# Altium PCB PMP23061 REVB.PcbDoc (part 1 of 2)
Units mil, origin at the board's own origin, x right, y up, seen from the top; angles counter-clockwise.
Board outline 3200 x 3250 mil, 2 copper layers (Top Layer, Bottom Layer), stack 64.8 mil thick; 102 components, 47 nets, 218 pads, 69 vias.
Unrouted connection lines stored in the file: 132.
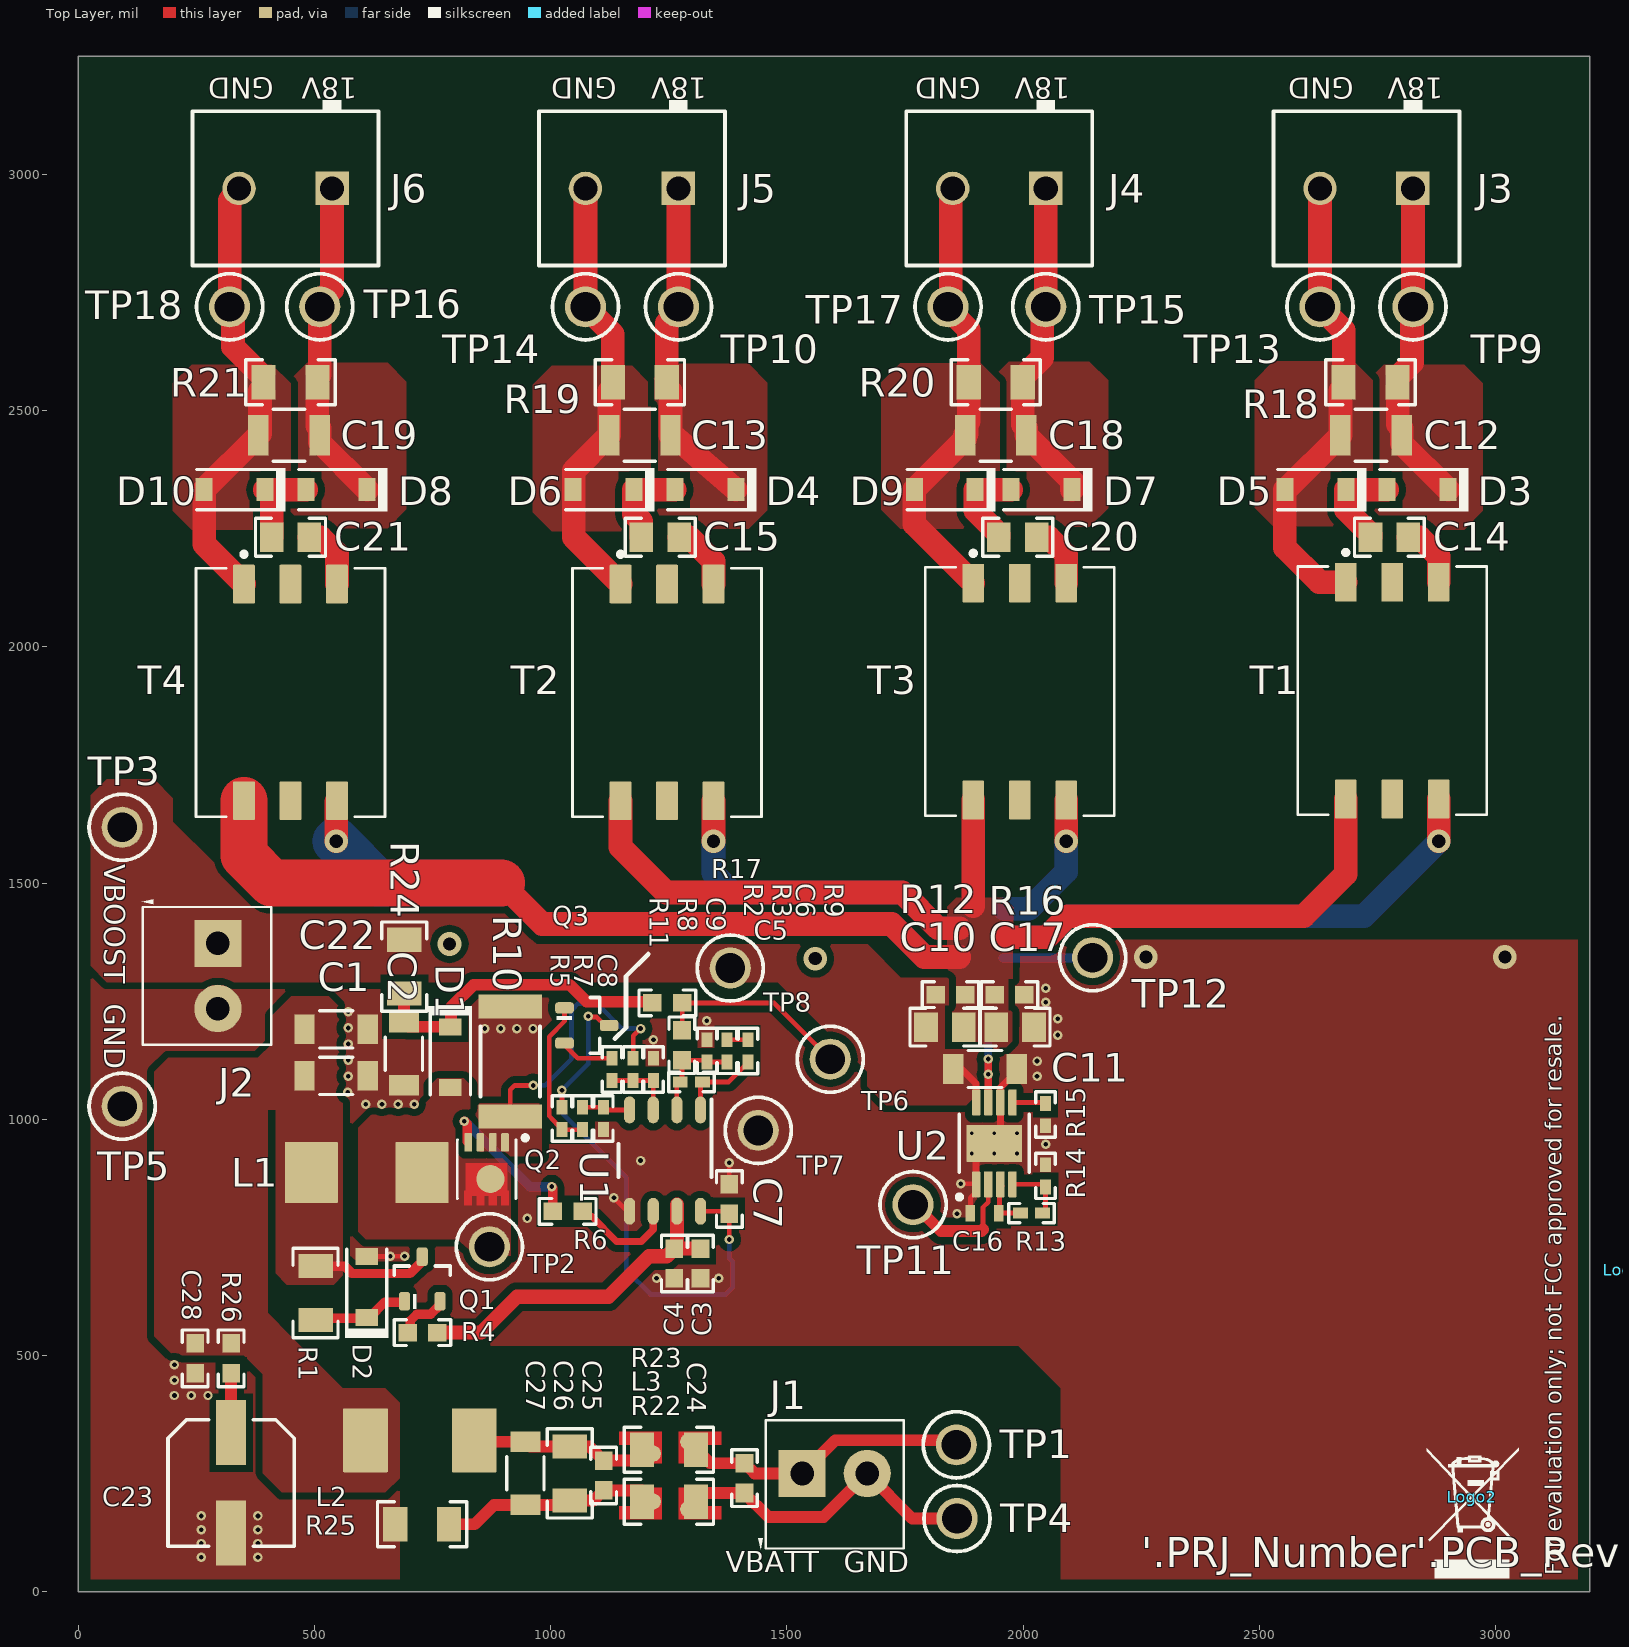
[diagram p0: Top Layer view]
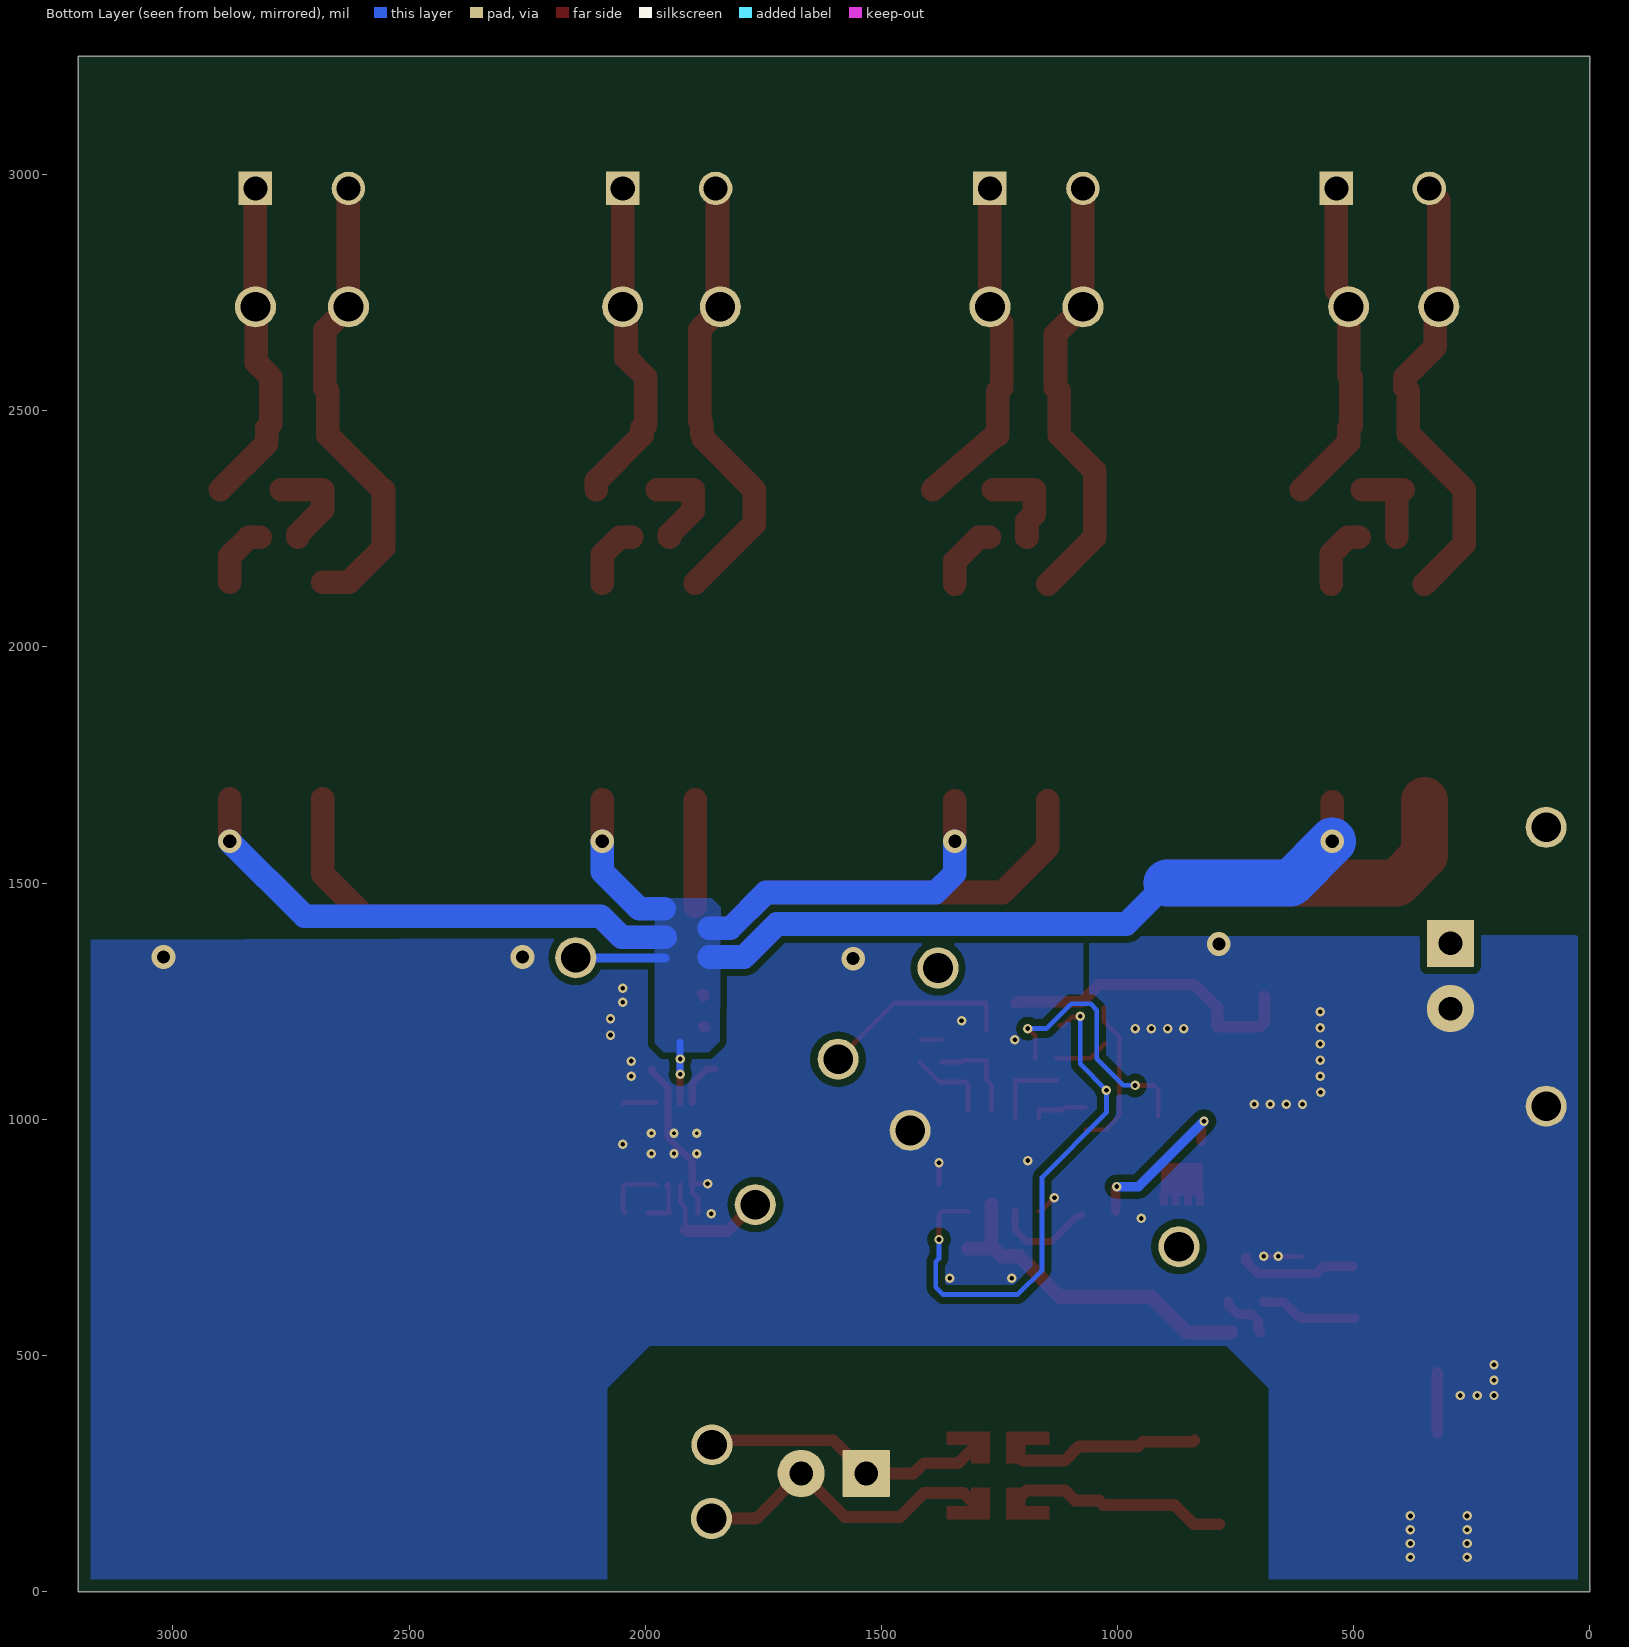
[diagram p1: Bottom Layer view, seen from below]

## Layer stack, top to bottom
Top Solder: solder mask 0.4, Solder Resist, Dk 3.5
Top Layer: signal copper 2.8
Dielectric1: core 59.2, FR-4 High Tg, Dk 4.8
Bottom Layer: signal copper 2.8
Bottom Solder: solder mask 0.4, Solder Resist, Dk 3.5

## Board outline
0,0 0,3250 3200,3250 3200,0

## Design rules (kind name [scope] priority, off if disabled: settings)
AcuteAngle [All] p1: minimum=4.50000000000000E+0001 checktracksonly=FALSE
AssemblyTestPointUsage [All] p1: valid=2
BoardOutlineClearance BoardOutlineClearance_MountingHoles [OnCopper and InComponentClass('Mounting Holes')] p1: gap=39.37 ignorepadtopadclearanceinfootprint=FALSE
BoardOutlineClearance BoardOutlineClearance_Poly [OnCopper and IsPoly] p2: gap=25 ignorepadtopadclearanceinfootprint=FALSE
BoardOutlineClearance [OnCopper and Not InComponentClass('Logo') and not InComponentClass('FiducialMark') and not InRegion(1000,500,4000,800) and not InPoly] p3: gap=40 ignorepadtopadclearanceinfootprint=FALSE
Clearance Clearance_Keepouts [((IsTrack Or IsArc) And Not InPoly) And IsFree and IsKeepOut vs ((IsTrack Or IsArc) And Not InPoly) And IsFree and IsKeepOut] p1: gap=0 ignorepadtopadclearanceinfootprint=FALSE
Clearance Clearance_Poly [InPolygon] p2: gap=15 ignorepadtopadclearanceinfootprint=TRUE
Clearance Clearance_FiducialMark [IsKeepOut and InComponentClass('FiducialMark') vs IsPad and InComponentClass('FiducialMark')] p3: gap=0 ignorepadtopadclearanceinfootprint=FALSE
Clearance [All] p4: gap=7.87 ignorepadtopadclearanceinfootprint=TRUE
ComponentClearance ComponentClearance_MountingHoles_FiducialMarks [InComponentClass('Mounting Holes') vs InComponentClass('FiducialMark')] p1: gap=50 collisioncheckmode=3 verticalgap=10 showdistances=FALSE
ComponentClearance ComponentClearance_Shunt [InComponentClass('Header') vs InComponentClass('Shunt')] p2: gap=0 collisioncheckmode=3 verticalgap=0 showdistances=FALSE
ComponentClearance ComponentClearance_Logo [InComponentClass('Logo')] p3: gap=30 collisioncheckmode=3 verticalgap=10 showdistances=FALSE
ComponentClearance ComponentClearance_ScrewToNut [(HasFootprint('NY PMS 440 0025 PH')) vs (HasFootprint('Keystone_1902C'))] p4: gap=5 collisioncheckmode=3 verticalgap=10 showdistances=FALSE
ComponentClearance ComponentClearance_MountingHoles [InComponentClass('Mounting Holes')] p5: gap=100 collisioncheckmode=3 verticalgap=100000 showdistances=FALSE
ComponentClearance ComponentClearance_SmallPassives [HasFootprint('0201*') or HasFootprint('0402*') or HasFootprint('0508') or HasFootprint('0603*') or HasFootprint('0612') or HasFootprint('0805*') or HasFootprint('0815*') or HasFootprint('0830*') or HasFootprint('1206*') or HasFootprint('1210*') or HasFootprint('1808*') or HasFootprint('1812*') or HasFootprint('1825*') or HasFootprint('2010*') or HasFootprint('2220*') or HasFootprint('2225*') or HasFootprint('2512*') or HasFootprint('2728*') or HasFootprint('3518*') vs HasFootprint('0201*') or HasFootprint('0402*') or HasFootprint('0508') or HasFootprint('0603*') or HasFootprint('0612') or HasFootprint('0805*') or HasFootprint('0815*') or HasFootprint('0830*') or HasFootprint('1206*') or HasFootprint('1210*') or HasFootprint('1808*') or HasFootprint('1812*') or HasFootprint('1825*') or HasFootprint('2010*') or HasFootprint('2220*') or HasFootprint('2225*') or HasFootprint('2512*') or HasFootprint('2728*') or HasFootprint('3518*')] p6: gap=14.96 collisioncheckmode=3 verticalgap=10 showdistances=FALSE
ComponentClearance ComponentClearance_THtoSMT [IsThruComponent vs IsSMTComponent] p7: gap=30 collisioncheckmode=3 verticalgap=30 showdistances=FALSE
ComponentClearance ComponentClearance_THtoTH [IsThruComponent vs IsThruComponent] p8: gap=20 collisioncheckmode=3 verticalgap=30 showdistances=FALSE
ComponentClearance [All] p9: gap=20 collisioncheckmode=3 verticalgap=10 showdistances=FALSE
DiffPairsRouting [All] p1: maxlimit=100 minlimit=10 mostfreqgap=10 toplayer_minwidth=15 toplayer_maxwidth=15 toplayer_prefwidth=15 bottomlayer_minwidth=15 bottomlayer_maxwidth=15 bottomlayer_prefwidth=15 maxuncoupledlength=1000
FabricationTestPointUsage TestPointUsage [All] p1: valid=2 allowmultiple=FALSE
FabricationTestpoint Testpoint [All] p1: side=3 testpointundercomponent=TRUE minsize=40 maxsize=100 preferedsize=60 minholesize=0 maxholesize=40 preferedholesize=32 testpointgrid=1 allowsidetop=TRUE allowsidebottom=TRUE usegrid=TRUE gridtolerance=0.01
FanoutControl Fanout_LCC [IsLCC] p1: bgadir=Out bgaviamode=Centered fanoutstyle=Auto fanoutdirection=Alternating viagrid=1 // Fanout_LCC (Default Rule)
FanoutControl Fanout_BGA [IsBGA] p2: bgadir=Out bgaviamode=Centered fanoutstyle=Auto fanoutdirection=Alternating viagrid=1 // Fanout_BGA (Default Rule)
FanoutControl Fanout_Default [All] p4: bgadir=Out bgaviamode=Centered fanoutstyle=Auto fanoutdirection=Alternating viagrid=1 // Fanout_Default (Default Rule)
FanoutControl Fanout_Small [(CompPinCount < 5)] p5: bgadir=Out bgaviamode=Centered fanoutstyle=Auto fanoutdirection=OutThenIn viagrid=1 // Fanout_Small (Default Rule)
HoleSize [All] p1: absolutevalues=TRUE maxlimit=251 minlimit=7.87 maxpercent=80.000 minpercent=20.000
MinimumAnnularRing MinimumAnnularRing_ThermalPadVias [IsVia and InAnyComponent] p1: minimumring=4.9
MinimumAnnularRing [All] p2: minimumring=4.9
MinimumSolderMaskSliver MinimumSolderMaskSliver_Logo [InComponentClass('Logo') vs InComponentClass('Logo')] p1: minsoldermaskwidth=0.7
MinimumSolderMaskSliver [All] p2: minsoldermaskwidth=3.94
PlaneClearance [All] p1: clearance=15
PlaneConnect [All] p1: planeconnectstyle=Direct reliefexpansion=10 reliefentries=4 reliefconductorwidth=10 reliefairgap=10
PolygonConnect [All] p1: connectstyle=Direct reliefconductorwidth=10 reliefentries=4 polygonreliefangle="90 Angle" airgapwidth=10
RoutingVias ThermalPadVias [IsVia and InAnyComponent] p1: holewidth=7.87 width=19.68 viastyle="Through Hole" minholewidth=7.87 minwidth=10 maxholewidth=12.99 maxwidth=23.62
RoutingVias [All] p2: holewidth=16 width=34 viastyle="Through Hole" minholewidth=7.87 minwidth=18 maxholewidth=40 maxwidth=65
SilkToBoardRegionClearance [Not ((IsComment or IsDesignator) And (Hide <> 'False')) and not InRegion(1000,500,4000,800)] p1:
SilkToSilkClearance SilkToSilkClearance_Pb-FreeLogo [(HasFootprint('Pb-Free_Overlay_Medium') OR HasFootprint('Pb-Free_Overlay_Small')) vs (HasFootprint('Pb-Free_Overlay_Medium') OR HasFootprint('Pb-Free_Overlay_Small'))] p1: silktosilkclearance=0
SilkToSilkClearance [All] p2: silktosilkclearance=0
SilkToSolderMaskClearance SilkToComponentPadClearance [(IsPad or IsFill or IsRegion) and InAnycomponent] p1: minsilkscreentomaskgap=0 clearancetoexposedcopper=TRUE
SilkToSolderMaskClearance "Silk to Solder Mask Opening" [All] p2: minsilkscreentomaskgap=0 clearancetoexposedcopper=FALSE
SolderMaskExpansion [All] p1: expansion=1.97 istentingtop=FALSE
UnRoutedNet [All] p1: checkbadconnections=TRUE
Width [All] p1: maxlimit=100 minlimit=6 preferedwidth=10 checkconnectedcopper=TRUE
13 further rules are at their usual default settings.

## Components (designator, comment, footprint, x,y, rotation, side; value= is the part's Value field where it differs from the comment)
C1 "CGA5L3X7R1H475K160AE" 1206_190 545.45,1091.81 r0 top value=4.7uF
C2 "CGA5L3X7R1H475K160AE" 1206_190 688.99,1138.75 r270 top value=4.7uF
C3 "CGA3E2X7R1H104K080AA" 0603 1316.9,694.58 r270 top value=0.1uF
C4 "GCM188R71E105KA64D" 0603 1261.58,694.58 r270 top value=1uF
C5 "CGA2B2C0G1H470J050BA" 0402 1297.76,1078.92 r180 top value=47pF
C6 "GCM155R71H222KA37D" 0402 1373.39,1144.66 r90 top value=2200pF
C7 "GCM188R71C105MA64D" 0603 1378.11,831.15 r90 top value=1uF
C8 "CGA2B2C0G1H101J050BA" 0402 1111.29,1001.58 r270 top value=100pF
C9 "CGA2B2C0G1H101J050BA" 0402 1217.29,1105.37 r90 top value=100pF
C10 "CGA4J3X7R1H105K125AB" 0805_HV 1834.42,1194.88 r0 top value=1uF
C11 "CGA5L3X7R1H475K160AE" 1206_190 1919.29,1106.3 r180 top value=4.7uF
C12 "CGA6P3X7R1H475K250AB" 1210_280 2736.79,2447.97 r180 top value=4.7uF
C13 "CGA6P3X7R1H475K250AB" 1210_280 1188.52,2447.97 r180 top value=4.7uF
C14 "CGA4J2C0G1H333J125AA" 0805_HV 2775.53,2232.07 r180 top value=0.033uF
C15 "CGA4J2C0G1H333J125AA" 0805_HV 1231.83,2232.07 r180 top value=0.033uF
C16 "CGA3E1X7R1E105K080AC" 0603S 1918.39,801.18 r180 top value=1uF
C17 "CGA4J3X7R1H105K125AB" 0805_HV 1983.07,1194.88 r0 top value=1uF
C18 "CGA6P3X7R1H475K250AB" 1210_280 1942.01,2447.97 r180 top value=4.7uF
C19 "CGA6P3X7R1H475K250AB" 1210_280 445.89,2447.97 r180 top value=4.7uF
C20 "CGA4J2C0G1H333J125AA" 0805_HV 1988.76,2232.07 r180 top value=0.033uF
C21 "CGA4J2C0G1H333J125AA" 0805_HV 448.84,2232.07 r180 top value=0.033uF
C22 "CGA5L3X7R1H475K160AE" 1206_190 545.45,1190.24 r0 top value=4.7uF
C23 "HHXA500ARA330MF80G" HXA_F80 323.18,230 r270 top value=33uF
C24 "CGA3E2X7R1H104K080AA" 0603 1410,240 r270 top value=0.1uF
C25 "CGA3E2X7R1H104K080AA" 0603 1111.8,245.59 r270 top value=0.1uF
C26 "CGA5L1X7R1H106K160AE" 1206 1040,250 r270 top value=10uF
C27 "UMK316B7105KLHT" 1206_180 946.27,250.36 r270 top value=1uF
C28 "CGA3E2X7R1H104K080AA" 0603 247.01,493.86 r270 top value=0.1uF
D1 "PMEG6010CEGWJ" SOD-123 787.42,1131.18 r270 top value=60V
D2 "MMSZ4694-HE3-08" SOD-123 610.25,644.78 r90 top value=8.2V
D3 "PMEG6010CEGWJ" SOD-123 2835.21,2333.02 r180 top value=60V
D4 "PMEG6010CEGWJ" SOD-123 1327.23,2333.02 r180 top value=60V
D5 "PMEG6010CEGWJ" SOD-123 2618.68,2333.02 r180 top value=60V
D6 "PMEG6010CEGWJ" SOD-123 1111.8,2333.02 r180 top value=60V
D7 "PMEG6010CEGWJ" SOD-123 2039.13,2333.02 r180 top value=60V
D8 "PMEG6010CEGWJ" SOD-123 546.54,2333.02 r180 top value=60V
D9 "PMEG6010CEGWJ" SOD-123 1834.01,2333.02 r180 top value=60V
D10 "PMEG6010CEGWJ" SOD-123 330,2333.02 r180 top value=60V
J1 "ED555/2DS" TERM_BLK_ED555-2DS 1532,250 r0 top
J2 "ED555/2DS" TERM_BLK_ED555-2DS 295.28,1372.25 r270 top
J3 "691213710002" Wurth_691213710002 2726.94,2970.73 r180 top
J4 "691213710002" Wurth_691213710002 1949.39,2970.73 r180 top
J5 "691213710002" Wurth_691213710002 1171.83,2970.73 r180 top
J6 "691213710002" Wurth_691213710002 438.41,2970.73 r180 top
L1 "SPM7054VT- 150M-D" "FP-SPM7054VT- 470M-D_STM_7MM5_7MM0-0" 610.25,887.08 r0 top
L2 "ETQP3M4R7KVN" FP-ETQP3M4R7KVN_SMT_6MM4_6MM0-MFG 722.8,320 r180 top
L3 "DLW5BTH142TQ2L" FP-DLW5BTH142TQ2L_SMT_5MM0_5MM0-MFG 1252.91,245.59 r0 top
Logo1 "FCC disclaimer" FCC_disclaimer 3280,680 r90 top
Logo2 "WEEE logo" WEEE_Minimum 2950,200 r0 top
Q1 "SMMBT2222ALT1G" SOT-23 727.86,661.76 r90 top value="40 V"
Q2 "SQ7414CENW" FP-SQ7414CENW_PowerPAK_1212-8W-SINGLE-MFG 864.06,894.32 r270 top
Q3 "SMMBT2222ALT1G" SOT-23 1076.24,1198.4 r0 top value="40 V"
R1 "CRCW12062K21FKEA" 1206 501.98,631.99 r90 top value=2.21k
R2 "CRCW0603140KFKEA" 0603 1277.69,1156.55 r90 top value=140k
R3 "CRCW040210K0FKED" 0402 1330.35,1144.66 r270 top value=10.0k
R4 "CRCW060350R0FKEA" 0603 728.36,548.2 r180 top value=50
R5 "CRCW040224K3FKED" 0402 1023.78,1001.58 r90 top value=24.3k
R6 "CRCW06033R01FKEA" 0603 1035.78,805.09 r180 top value=3.01
R7 "CRCW04026K04FKED" 0402 1067.29,1001.58 r90 top value=6.04k
R8 "CRCW04021K00FKED" 0402 1174.38,1105.37 r90 top value=1.00k
R9 "CRCW040249K9FKED" 0402 1417.49,1144.47 r270 top value=49.9k
R10 "ERJ-L1WKF10CU" 2512 914,1122.14 r270 top value=0.1
R11 "CRCW04023K01FKED" 0402 1129.29,1105.37 r270 top value=3.01k
R12 "CRCW060310K0FKEA" 0603 1846.23,1263.78 r180 top value=10.0k
R13 "CRCW04023K24FKED" 0402 2017.72,801.18 r180 top value=3.24k
R14 "CRCW040211K0FKED" 0402 2047.24,879.92 r270 top value=11.0k
R15 "CRCW0402100KFKED" 0402 2047.24,1009.84 r90 top value=100k
R16 "CRCW060310K0FKEA" 0603 1971.26,1263.78 r180 top value=10.0k
R17 "CRCW060349R9FKEA" 0603 1246.59,1246.2 r180 top value=49.9
R18 "CRCW120620K0FKEA" 1206 2735.53,2560 r0 top value=20.0k
R19 "CRCW120620K0FKEA" 1206 1188.52,2560 r0 top value=20.0k
R20 "CRCW120620K0FKEA" 1206 1942.01,2560 r0 top value=20.0k
R21 "CRCW120620K0FKEA" 1206 448.84,2560 r0 top value=20.0k
R22 "CRCW12060000Z0EA" 1206 1250,300 r180 top value=0
R23 "CRCW12060000Z0EA" 1206 1250,190 r180 top value=0
R24 "CRCW12060000Z0EA" 1206 690,1322.91 r90 top value=0
R25 "CRCW12060000Z0EA" 1206 727.59,142.26 r180 top value=0
R26 "CRCW06031R00FKEA" 0603 323.18,493.86 r90 top value=1.00
T1 "750319177" FP-750319177_SMT_XFRMR_13MM36_10MM16-MFG 2781.52,1907.48 r90 top
T2 "750319177" FP-750319177_SMT_XFRMR_13MM36_10MM16-MFG 1246.08,1903.54 r90 top
T3 "750319177" FP-750319177_SMT_XFRMR_13MM36_10MM16-MFG 1992.81,1905.51 r90 top
T4 "750319177" FP-750319177_SMT_XFRMR_13MM36_10MM16-MFG 448.84,1903.54 r90 top
TP1 "5010" Keystone5010 1858.65,310.55 r0 top
TP2 "5010" Keystone5010 870,730 r270 top
TP3 "5010" Keystone5010 92.56,1618.11 r90 top
TP4 "5011" Keystone5011 1860.01,154.57 r0 top
TP5 "5011" Keystone5011 92.56,1027.56 r0 top
TP6 "5012" Keystone5012 1591.65,1126.96 r0 top
TP7 "5011" Keystone5011 1439.14,976.35 r90 top
TP8 "5010" Keystone5010 1380,1320 r0 top
TP9 "5010" Keystone5010 2825.37,2720 r0 top
TP10 "5010" Keystone5010 1270.25,2720 r0 top
TP11 "5014" Keystone5014 1767.05,819.02 r0 top
TP12 "5010" Keystone5010 2147.13,1341.89 r0 top
TP13 "5011" Keystone5011 2628.52,2720 r0 top
TP14 "5011" Keystone5011 1073.4,2720 r0 top
TP15 "5010" Keystone5010 2047.81,2720 r0 top
TP16 "5010" Keystone5010 510.85,2720 r0 top
TP17 "5011" Keystone5011 1841.12,2720 r0 top
TP18 "5011" Keystone5011 320,2720 r0 top
U1 "UCC2803QDRQ1" D0008A_N 1241.9,912.37 r270 top
U2 "UCC25800DGNRQ1" DGN0008G-MFG 1938.98,948.82 r90 top

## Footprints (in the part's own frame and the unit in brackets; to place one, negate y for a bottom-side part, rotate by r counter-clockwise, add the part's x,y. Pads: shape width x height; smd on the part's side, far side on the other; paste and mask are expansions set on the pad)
0402 [mm] "0402 from SM-752 data"
  rect 0.8x0.6 smd: 1(-0.6,0) 2(0.6,0)
  silkscreen extent -1.22,-0.52 1.22,0.52, body extent -0.55,-0.3 0.55,0.3, height 0.6
0603 [mm] "0603 from SM-752 data"
  rect 1x0.95 smd: 1(-0.8,0) 2(0.8,0)
  silkscreen extent -1.52,-0.69 1.52,0.69, body extent -0.87,-0.47 0.87,0.47, height 1
0603S [mil]
  rect 20x35 smd: 1(-30,0) 2(30,0)
  body extent -34,-19 34,19, height 39
0805_HV [mil] "0805 with 30mil clearance between pads"
  rect 50x63 smd: 1(-40,0) 2(40,0)
  silkscreen extent -74,-40 74,40, body extent -43,-29 43,29, height 57
1206 [mm] "1206 from SM-752 data"
  rect 1.3x1.85 smd: 1(-1.45,0) 2(1.45,0)
  silkscreen extent -2.4,-1.21 2.4,1.21, body extent -1.7,-0.9 1.7,0.9, height 1.35
1206_180 [mm] "1206_180"
  rect 1.1x1.6 smd: 1(-1.7,0) 2(1.7,0)
  silkscreen extent -0.9,-1 0.9,1, body extent -1.75,-0.95 1.75,0.95, height 1.8
1206_190 [mm] "1206_190"
  rect 1.1x1.6 smd: 1(-1.7,0) 2(1.7,0)
  silkscreen extent -0.9,-1 0.9,1, body extent -1.75,-0.95 1.75,0.95, height 1.9
1210_280 [mm] "SMD, 2-Leads, Body 3.6x2.8mm, Height 2.8mm"
  rect 1.1x2.2 smd: 1(-1.65,0) 2(1.65,0)
  silkscreen extent -0.84,-1.4 0.84,1.4, body extent -1.8,-1.4 1.8,1.4, height 2.8
2512 [mm] "Chip Resistor, Body 6.3x3.2mm, IPC Medium Density"
  rect 1.3x3.4 smd: 1(-2.95,0) 2(2.95,0)
  silkscreen extent -1.9,-1.6 1.9,1.6, body extent -3.22,-1.67 3.22,1.67, height 0.71
D0008A_N [mm] "SOIC, 8-Leads, Body 4.9x3.9mm, Pitch 1.27mm, IPC Medium Density"
  oval 1.45x0.6 smd: 1(-2.725,1.905) 2(-2.725,0.635) 3(-2.725,-0.635) 4(-2.725,-1.905) 5(2.725,-1.905) 6(2.725,-0.635) 7(2.725,0.635) 8(2.725,1.905)
  silkscreen extent -3.3,-2.5 0.9,2.5, body extent -3,-2.45 3,2.45, height 1.63
DGN0008G-MFG [mm]
  rrect22% 1.4x0.45 smd paste+0 mask+0: 1(-2.2,0.975) 2(-2.2,0.325) 3(-2.2,-0.325) 4(-2.2,-0.975) 5(2.2,-0.975) 6(2.2,-0.325) 7(2.2,0.325) 8(2.2,0.975)
  rrect5% 2x3 smd paste-1000 mask-1000: 9(0,0)
  silkscreen extent -3.01,-1.88 1.55,2, body extent -3,-1.8 3,1.8, height 0.25
FCC_disclaimer [mil]
FP-750319177_SMT_XFRMR_13MM36_10MM16-MFG [mm]
  rrect9% 2.08x1.17 smd paste+0 mask+0: 1(5.83,2.5) 2(5.83,0) 3(5.83,-2.5) 4(-5.83,-2.5) 5(-5.83,0) 6(-5.83,2.5)
  silkscreen extent -6.68,-5.08 7.55,5.08, body extent -6.97,-5.18 6.97,5.18, height 0.25
FP-DLW5BTH142TQ2L_SMT_5MM0_5MM0-MFG [mil]
  round 35.31 smd paste+0 mask+0: 1(38.63,71.6) 4(38.63,-71.6)
  round 34.99 smd paste+0 mask+0: 2(-37.16,46.51) 3(-37.16,-54.87)
  Top Layer region: -108.27,64.96 -108.27,92.52 -17.72,92.52 -17.72,25.59 -57.09,25.59 -57.09,64.96
  Top Layer region: 108.27,64.96 108.27,92.52 17.72,92.52 17.72,25.59 57.09,25.59 57.09,64.96
  Top Layer region: -108.27,-64.96 -108.27,-92.52 -17.72,-92.52 -17.72,-25.59 -57.09,-25.59 -57.09,-64.96
  Top Layer region: 108.27,-64.96 108.27,-92.52 17.72,-92.52 17.72,-25.59 57.09,-25.59 57.09,-64.96
  body extent -112,-108 112,108, height 10
FP-ETQP3M4R7KVN_SMT_6MM4_6MM0-MFG [mil]
  rrect4% 95x135 smd paste+0 mask+0: 1(-115,0) 2(115,0)
  body extent -166,-138 166,138, height 10
"FP-SPM7054VT- 470M-D_STM_7MM5_7MM0-0" [mm]
  rrect4% 2.85x3.3 smd paste+0 mask+0: 1(-2.975,0) 2(2.975,0)
  body extent -4.5,-3.8 4.5,3.8, height 0.25
FP-SQ7414CENW_PowerPAK_1212-8W-SINGLE-MFG [mil]
  rrect25% 39x16 smd paste+0 mask+0: 1(-56.5,39) 2(-56.5,13) 3(-56.5,-13) 4(-56.5,-39)
  round 59.4 smd paste+0 mask+0: 5-6-7-8(21,8)
  Top Layer region: -12,44 46,44 46,47 76,47 76,31 56,31 56,21 76,21 76,5 56,5 56,-5 76,-5 76,-21 56,-21 56,-31 76,-31 76,-47 46,-47 46,-44 -12,-44
  silkscreen extent -71,-62 62,87, body extent -65,-65 65,65, height 46
HXA_F80 [mm] "SMD, 2-Leads, Dia 6.3mm"
  rect 3.5x1.6 smd: 1(-2.7,0) 2(2.7,0)
  silkscreen extent -3.4,-3.4 3.4,3.4, body extent -3.4,-3.4 3.4,3.4, height 8.01
Keystone5010 [mil] "Keystone Multipurpose loops"
  round 87 hole 63: 1(0,0)
  silkscreen extent -70,-70 70,70, body extent -63,-63 63,62, height 319
Keystone5011 [mil] "Keystone Multipurpose loops"
  round 87 hole 63: 1(0,0)
  silkscreen extent -70,-70 70,70, body extent -63,-63 63,62, height 319
Keystone5012 [mil] "Keystone Multipurpose loops"
  round 87 hole 63: 1(0,0)
  silkscreen extent -70,-70 70,70, body extent -63,-63 63,62, height 319
Keystone5014 [mil] "Keystone Multipurpose loops"
  round 87 hole 63: 1(0,0)
  silkscreen extent -70,-70 70,70, body extent -63,-63 63,62, height 319
SOD-123 [mm] "On Semi recommended land pattern"
  rect 0.915x1.22 smd: 1(-1.637,0) 2(1.637,0)
  silkscreen extent -2.74,-1.17 2.03,1.17, body extent -1.93,-0.9 1.93,0.9, height 1.35
SOT-23 [mm] "SOT23, 3-Leads, Body 2.9x1.3mm, Pitch 0.95mm, Lead Span 2.5mm, IPC Medium Density"
  rrect50% 1x0.6 smd: 1(-1.2,0.95) 2(-1.2,-0.95) 3(1.2,0)
  silkscreen extent -1.62,-1.5 0.7,1.5, body extent -1.16,-1.45 1.21,1.45, height 1
TERM_BLK_ED555-2DS [mil]
  rrect4% 100x100 hole 50: 1(0,0)
  round 100 hole 50: 2(138,0)
  silkscreen extent -93,-161 215,113, body extent -69,-150 207,106, height 323
WEEE_Minimum [mil] "WEEElie bin"
  silkscreen extent -95,-172 99,104
Wurth_691213710002 [mm] "TH, 2-Leads, Body 10x8.3mm, Pitch 5mm"
  rect 1.8x1.8 hole 1.3: 1(-2.5,0)
  round 1.8 hole 1.3: 2(2.5,0)
  silkscreen extent -5,-4.75 5,4.15, body extent -5.6,-4.15 5,4.15, height 10

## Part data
C1 C2 C11 C22: library part CMP-0085349-1, "CAP, CERM, 4.7 µF, 50 V,+/- 10%, X7R, AEC-Q200 Grade 1, 1206", Cap_Case=1206, Manufacturer=TDK, TempCo=X7R, Tolerance_%=10%, Value2=50V, ValueDisplayed=4.7µF
C3 C24 C25 C28: library part CMP-0007078-4, "CAP, CERM, 0.1 uF, 50 V, +/- 10%, X7R, AEC-Q200 Grade 1, 0603", Cap_Case=0603, Manufacturer=TDK, Supplier Part Number 1=445-5666-1-ND, TempCo=X7R, Tolerance_%=10%, Value1="0.0296 ohm", Value2=50V, ValueDisplayed=0.1uF
C4: library part CMP-0007139-4, "CAP, CERM, 1 uF, 25 V, +/- 10%, X7R, AEC-Q200 Grade 1, 0603", Cap_Case=0603, Manufacturer=MuRata, Supplier Part Number 1=490-10673-1-ND, TempCo=X7R, Tolerance_%=10%, Value1=Unknown, Value2=25V, ValueDisplayed=1uF
C5: library part CMP-0860832-1, "CAP, CERM, 47 pF, 50 V,+/- 5%, C0G/NP0, AEC-Q200 Grade 1, 0402", Cap_Case=0402, Manufacturer=TDK, TempCo=C0G/NP0, Tolerance_%=5%, Value2=50V, ValueDisplayed=47pF
C6: library part CMP-0006357-2, "CAP, CERM, 2200 pF, 50 V, +/- 10%, X7R, AEC-Q200 Grade 1, 0402", Cap_Case=0402, Manufacturer=MuRata, Supplier Part Number 1=490-4914-1-ND, TempCo=X7R, Tolerance_%=10%, Value1=Unknown, Value2=50V, ValueDisplayed=2200pF
C7: library part CMP-0007137-5, "CAP, CERM, 1 uF, 16 V, +/- 20%, X7R, AEC-Q200 Grade 1, 0603", Cap_Case=0603, Manufacturer=MuRata, TempCo=X7R, Tolerance_%=20%, Value1=Unknown, Value2=16V, ValueDisplayed=1uF
C8 C9: library part CMP-0006308-2, "CAP, CERM, 100 pF, 50 V, +/- 5%, C0G/NP0, AEC-Q200 Grade 1, 0402", Cap_Case=0402, Manufacturer=TDK, Supplier Part Number 1=445-5596-1-ND, TempCo=C0G/NP0, Tolerance_%=5%, Value1=Unknown, Value2=50V, ValueDisplayed=100pF
C10 C17: library part CMP-0007976-2, "CAP, CERM, 1 uF, 50 V, +/- 10%, X7R, AEC-Q200 Grade 1, 0805", Cap_Case=0805, Manufacturer=TDK, Supplier Part Number 1=445-6961-1-ND, TempCo=X7R, Tolerance_%=10%, Value1="0.008782 ohm", Value2=50V, ValueDisplayed=1uF
C12 C13 C18 C19: library part CMP-0009162-2, "CAP, CERM, 4.7 uF, 50 V, +/- 10%, X7R, AEC-Q200 Grade 1, 1210", Cap_Case=1210_280, Manufacturer=TDK, Supplier Part Number 1=445-6999-1-ND, TempCo=X7R, Tolerance_%=10%, Value1="0.003166 ohm", Value2=50V, ValueDisplayed=4.7uF
C14 C15 C20 C21: library part CMP-0080742-1, "CAP, CERM, 0.033 µF, 50 V,+/- 5%, C0G/NP0, AEC-Q200 Grade 1, 0805", Cap_Case=0805, Manufacturer=TDK, Supplier Part Number 1=445-6950-1-ND, TempCo=C0G/NP0, Tolerance_%=5%, Value2=50V, ValueDisplayed=0.033µF
C16: library part CMP-0076705-3, "CAP, CERM, 1 µF, 25 V,+/- 10%, X7R, AEC-Q200 Grade 1, 0603", Cap_Case=1.6x0.8x0.8mm, Manufacturer=TDK, Supplier Part Number 1=445-6931-1-ND, TempCo=X7R, Tolerance_%=10%, Value2=25V, ValueDisplayed=1µF
C23: library part CMP-0012264-3, "CAP, Aluminum Polymer, 33 uF, 50 V, +/- 20%, 0.04 ohm, AEC-Q200 Grade 1, D6.3xL7.7mm SMD", Cap_Case=6.3x7.7mm, Manufacturer=Chemi-Con, Supplier Part Number 1=565-4167-1-ND, Tolerance_%=20%, Value1="0.04 ohm", Value2=50V, ValueDisplayed=33uF
C26: library part CMP-0860898-1, "CAP, CERM, 10 µF, 50 V,+/- 10%, X7R, AEC-Q200 Grade 1, 1206", Cap_Case=1206, Manufacturer=TDK, TempCo=X7R, Tolerance_%=10%, Value2=50V, ValueDisplayed=10µF
C27: library part CMP-0080106-1, "CAP, CERM, 1 µF, 50 V,+/- 10%, X7R, AEC-Q200 Grade 1, 1206", Cap_Case=1206, Manufacturer="Taiyo Yuden", Supplier Part Number 1=587-3518-1-ND, TempCo=X7R, Tolerance_%=10%, Value2=50V, ValueDisplayed=1µF
D1 D3 D4 D5 D6 D7 D8 D9 D10: library part CMP-0079239-2, "Diode, Schottky, 60 V, 1 A, AEC-Q101, SOD-123", Manufacturer=Nexperia, Value1=1A, Value2=0.66V
D2: library part CMP-0077567-3, "Diode, Zener, 8.2 V, 500 mW, AEC-Q101, SOD-123", Manufacturer=Vishay-Semiconductor, Power_W=500mW, Value1=0.5W
J1 J2: library part CMP-0074913-1, "Terminal Block, 3.5mm Pitch, 2x1, TH", Color=Grey, Current_A=6A, Manufacturer="On-Shore Technology", Supplier Part Number 1=ED1514-ND, Voltage_V=150V
J3 J4 J5 J6: library part CMP-0054823-2, "Terminal Block, 2x1, Brass, TH", Color=Green, Manufacturer="Wurth Elektronik", Supplier Part Number 1=732-2038-ND
L1: library part CMP-0088010-1, "SMD Power Inductor", Manufacturer=TDK
L2: library part CMP-0086492-1, "4.7µH Shielded  Inductor 5.6A 31.9 mOhm Max 2-SMD, J-Lead", Manufacturer=Panasonic
L3: library part CMP-0087211-1, "Wire Wound Chip Common Mode Choke Coil", Manufacturer=Murata
Logo1: library part CMP-0074847-1, "FCC_disclaimer"
Logo2: library part CMP-0074769-1
Q1 Q3: library part CMP-0750169-1, "Transistor, NPN, 40 V, 0.6 A, AEC-Q101, SOT-23", Manufacturer="ON Semiconductor", Value1="0.6 A"
Q2: library part CMP-0092401-1, "N-Channel 18A (Tc) 62W (Tc) Surface Mount PowerPAK® 1212-8W", Digikey Part Number=SQ7414CENW-T1_GE3CT-ND, Drain To Source Breakdown Voltage=60V, Input Capacitace At Vds="1275pF @ 30V", Manufacturer=Vishay, Mouser Part Number=78-SQ7414CENW-T1_GE3, Operating Temperature Range="-55°C to +175°C", Power_W=62W, Pulse Drain Current=72A, Typ Forward Diode Voltage=0.8V
R1: library part CMP-0016848-3, "RES, 2.21 k, 1%, 0.25 W, AEC-Q200 Grade 0, 1206", Manufacturer=Vishay-Dale, Power_W=250mW, Supplier Part Number 1=541-2.21KFCT-ND, TempCo="100 ppm/C", Tolerance_%=1%, Value2=0.25W, Value_Code=2k21, ValueDisplayed=2.21k
R2: library part CMP-0022048-4, "RES, 140 k, 1%, 0.1 W, AEC-Q200 Grade 0, 0603", Manufacturer=Vishay-Dale, Power_W=100mW, Supplier Part Number 1=541-140KHCT-ND, TempCo="100 ppm/C", Tolerance_%=1%, Value2=0.1W, Value_Code=140k
R3: library part CMP-0025958-3, "RES, 10.0 k, 1%, 0.063 W, AEC-Q200 Grade 0, 0402", Manufacturer=Vishay-Dale, Power_W=63mW, Supplier Part Number 1=541-10.0KLCT-ND, TempCo="100 ppm/C", Tolerance_%=1%, Value2=0.063W, Value_Code=10k0, ValueDisplayed=10.0k
R4: library part CMP-0022479-4, "RES, 50, 1%, 0.1 W, AEC-Q200 Grade 0, 0603", Manufacturer=Vishay-Dale, Power_W=100mW, Supplier Part Number 1=89M6778, TempCo="100 ppm/C", Tolerance_%=1%, Value2=0.1W, Value_Code=50R0, ValueDisplayed=50
R5: library part CMP-0026195-2, "RES, 24.3 k, 1%, 0.063 W, AEC-Q200 Grade 0, 0402", Manufacturer=Vishay-Dale, Power_W=63mW, Supplier Part Number 1=541-24.3KLCT-ND, TempCo="100 ppm/C", Tolerance_%=1%, Value2=0.063W, Value_Code=24k3, ValueDisplayed=24.3k
R6: library part CMP-0022396-4, "RES, 3.01, 1%, 0.1 W, AEC-Q200 Grade 0, 0603", Manufacturer=Vishay-Dale, Power_W=100mW, Supplier Part Number 1=541-3.01HHCT-ND, TempCo="100 ppm/C", Tolerance_%=1%, Value2=0.1W, Value_Code=3R01, ValueDisplayed=3.01
R7: library part CMP-0026512-2, "RES, 6.04 k, 1%, 0.063 W, AEC-Q200 Grade 0, 0402", Manufacturer=Vishay-Dale, Power_W=63mW, Supplier Part Number 1=541-6.04KLCT-ND, TempCo="100 ppm/C", Tolerance_%=1%, Value2=0.063W, Value_Code=6k04, ValueDisplayed=6.04k
R8: library part CMP-0026071-3, "RES, 1.00 k, 1%, 0.063 W, AEC-Q200 Grade 0, 0402", Manufacturer=Vishay-Dale, Power_W=63mW, Supplier Part Number 1=541-1.00KLCT-ND, TempCo="100 ppm/C", Tolerance_%=1%, Value2=0.063W, Value_Code=1k00, ValueDisplayed=1.00k
R9: library part CMP-0026403-2, "RES, 49.9 k, 1%, 0.063 W, AEC-Q200 Grade 0, 0402", Manufacturer=Vishay-Dale, Power_W=63mW, Supplier Part Number 1=541-49.9KLCT-ND, TempCo="100 ppm/C", Tolerance_%=1%, Value2=0.063W, Value_Code=49k9, ValueDisplayed=49.9k
R10: library part CMP-0015806-2, "RES, 0.1, 1%, 1 W, 2512", Manufacturer=Panasonic, Power_W=1W, Supplier Part Number 1=1577587, TempCo="100 ppm/C", Tolerance_%=1%, Value_Code=R100, ValueDisplayed=0.1
R11: library part CMP-0026329-2, "RES, 3.01 k, 1%, 0.063 W, AEC-Q200 Grade 0, 0402", Manufacturer=Vishay-Dale, Power_W=63mW, Supplier Part Number 1=541-3.01KLCT-ND, TempCo="100 ppm/C", Tolerance_%=1%, Value2=0.063W, Value_Code=3k01, ValueDisplayed=3.01k
R12 R16: library part CMP-0021998-4, "RES, 10.0 k, 1%, 0.1 W, AEC-Q200 Grade 0, 0603", Manufacturer=Vishay-Dale, Power_W=100mW, Supplier Part Number 1=541-10.0KHCT-ND, TempCo="100 ppm/C", Tolerance_%=1%, Value2=0.1W, Value_Code=10k0, ValueDisplayed=10.0k
R13: library part CMP-0026332-2, "RES, 3.24 k, 1%, 0.063 W, AEC-Q200 Grade 0, 0402", Manufacturer=Vishay-Dale, Power_W=63mW, Supplier Part Number 1=541-3.24KLCT-ND, TempCo="100 ppm/C", Tolerance_%=1%, Value2=0.063W, Value_Code=3k24, ValueDisplayed=3.24k
R14: library part CMP-0025975-3, "RES, 11.0 k, 1%, 0.063 W, AEC-Q200 Grade 0, 0402", Manufacturer=Vishay-Dale, Power_W=63mW, Supplier Part Number 1=541-11.0KLCT-ND, TempCo="100 ppm/C", Tolerance_%=1%, Value2=0.063W, Value_Code=11k0, ValueDisplayed=11.0k
R15: library part CMP-0025950-3, "RES, 100 k, 1%, 0.063 W, AEC-Q200 Grade 0, 0402", Manufacturer=Vishay-Dale, Power_W=63mW, Supplier Part Number 1=541-100KLCT-ND, TempCo="100 ppm/C", Tolerance_%=1%, Value2=0.063W, Value_Code=100k
R17: library part CMP-0022448-4, "RES, 49.9, 1%, 0.1 W, AEC-Q200 Grade 0, 0603", Manufacturer=Vishay-Dale, Power_W=100mW, Supplier Part Number 1=541-49.9HCT-ND, TempCo="100 ppm/C", Tolerance_%=1%, Value2=0.1W, Value_Code=49R9, ValueDisplayed=49.9
R18 R19 R20 R21: library part CMP-0016779-3, "RES, 20.0 k, 1%, 0.25 W, AEC-Q200 Grade 0, 1206", Manufacturer=Vishay-Dale, Power_W=250mW, Supplier Part Number 1=541-20.0KFCT-ND, TempCo="100 ppm/C", Tolerance_%=1%, Value2=0.25W, Value_Code=20k0, ValueDisplayed=20.0k
R22 R23 R24 R25: library part CMP-0018573-3, "RES, 0, 5%, 0.25 W, AEC-Q200 Grade 0, 1206", Manufacturer=Vishay-Dale, Power_W=250mW, Supplier Part Number 1=541-0.0ECT-ND, TempCo="200 ppm/C", Tolerance_%=5%, Value2=0.25W, Value_Code=0000, ValueDisplayed=0
R26: library part CMP-0022170-4, "RES, 1.00, 1%, 0.1 W, AEC-Q200 Grade 0, 0603", Manufacturer=Vishay-Dale, Power_W=100mW, Supplier Part Number 1=52K8059, TempCo="100 ppm/C", Tolerance_%=1%, Value2=0.1W, Value_Code=1R00, ValueDisplayed=1.00
T1 T2 T3 T4: library part CMP-0090831-1, "Transformer, 1:1.67, 0.045Ohm Pri, 0.122 Sec, 16.5uH, 13.36x10.16x8.64mm", Frequency_Fixed=500kHz, Manufacturer="Wurth Electronics", Operating Temperature Range="-40°C to +125°C", ValueDisplayed=1.3pF
TP1 TP2 TP3 TP8 TP9 TP10 TP12 TP15 TP16: library part CMP-0055147-1, "Test Point, Multipurpose, Red, TH", Color=Red, Manufacturer=Keystone, Supplier Part Number 1=36-5010-ND
TP4 TP5 TP7 TP13 TP14 TP17 TP18: library part CMP-0055148-1, "Test Point, Multipurpose, Black, TH", Color=Black, Manufacturer=Keystone, Supplier Part Number 1=36-5011-ND
TP6: library part CMP-0055149-1, "Test Point, Multipurpose, White, TH", Color=White, Manufacturer=Keystone, Supplier Part Number 1=36-5012-ND
TP11: library part CMP-0055151-1, "Test Point, Multipurpose, Yellow, TH", Color=Yellow, Manufacturer=Keystone, Supplier Part Number 1=36-5014-ND
U1: library part CMP-0074136-1, "Automotive Low-Power BiCMOS Current-Mode PWM, D0008A (SOIC-8)", Alternate Manufacturer="Texas Instruments"
U2: library part CMP-0088494-2, "Open Loop LLC Transformer Driver for Isolated Bias Supplies", Manufacturer="Texas Instruments", Max Supply Voltage=36V, Min Supply Voltage=12V, Nominal Supply Current=500uA, Operating Temperature Range="-40°C to +150°C", Switching Frequency=100-2000kHz

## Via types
v1: diameter 20, hole 10, Top Layer to Bottom Layer, 55 vias
v2: diameter 50, hole 28, Top Layer to Bottom Layer, 8 vias
v3: diameter 19.68, hole 7.87, Top Layer to Bottom Layer, 6 vias

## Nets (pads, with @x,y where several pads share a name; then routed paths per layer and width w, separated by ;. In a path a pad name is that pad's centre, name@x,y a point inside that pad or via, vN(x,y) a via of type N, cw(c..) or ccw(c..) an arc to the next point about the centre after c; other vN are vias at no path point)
30V: C10.1 C11.2 J2.1 R12.2 R24.2 TP3.1 TP8.1 U2.8 | length 101.1
  Top Layer w15: C11.2@1852.36,1106.3 1869.82,1106.3 1900.59,1075.52 U2.8@1900.59,1035.43
30V_INT: C2.1 D1.1 R17.2 R24.1 | length 661.1
  Top Layer w25: R24.1@690,1260 688.99,1258.99 C2.1@688.99,1205.68 699.02,1195.65 D1.1@787.42,1195.65 788.52,1196.75 788.52,1236.52 836.66,1284.66 1039.69,1284.66 1075.78,1248.57 1212.72,1248.57 R17.2@1215.09,1246.2
BJT_VCC: D2.1 Q1.1 R1.1 | length 205.8
  Top Layer w20: R1.1@497.87,578.48 D2.1@609.07,578.48 ; D2.1@610.25,580.31 616.26,580.31 648.24,612.3 688.65,612.3 690.46,614.11 Q1.1@690.46,614.51
COMP: C5.1 R9.2 U1.1 | length 175.5
  Top Layer w10: U1.1@1316.9,1019.66 1316.9,1074.43 C5.1@1321.38,1078.92 1377.04,1078.92 1417.49,1119.37 R9.2@1417.49,1120.85
CS: C9.1 R8.1 R11.2 U1.3 | length 167
  Top Layer w10: R11.2@1129.29,1081.75 R8.1@1174.38,1081.75 C9.1@1217.29,1081.75 1216.9,1081.35 U1.3@1216.9,1019.66 U1.3@1216.9,1002.92
CSR: Q2.1 Q2.2 Q2.3 R8.2 R10.2 | length 557.6
  Top Layer w10: R10.2@914,1006 914,1061.97 923.45,1071.41 v1(962.94,1071.41) ; R8.2@1174.38,1128.99 1174.38,1176.28 v1(1190,1191.9)
  Bottom Layer w10: v1@964.29,1071.82 988.05,1071.82 1044.01,1127.78 1044.01,1231.13 1057.15,1244.27 1098.39,1244.27 1150.76,1191.9 v1(1190,1191.9)
FB: C5.2 C6.1 R2.1 R3.2 U1.2 | length 207.5
  Top Layer w10: U1.2@1266.9,1019.66 1266.9,1072.11 1273.71,1078.92 C5.2@1274.14,1078.92 1277.69,1082.47 R2.1@1277.69,1125.05 1326.33,1125.05 R3.2@1330.35,1121.04 C6.1@1373.39,1121.04
GATE: Q2.4 R6.2 | length 340.9
  Top Layer w20: v1(817.06,995.85) 823.06,989.85 Q2.4@823.06,952.82 ; v1(1001.78,857.3) 1004.28,854.8 R6.2@1004.28,805.09
  Bottom Layer w20: v1(817.06,995.85) 955.61,857.3 v1(1001.78,857.3)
